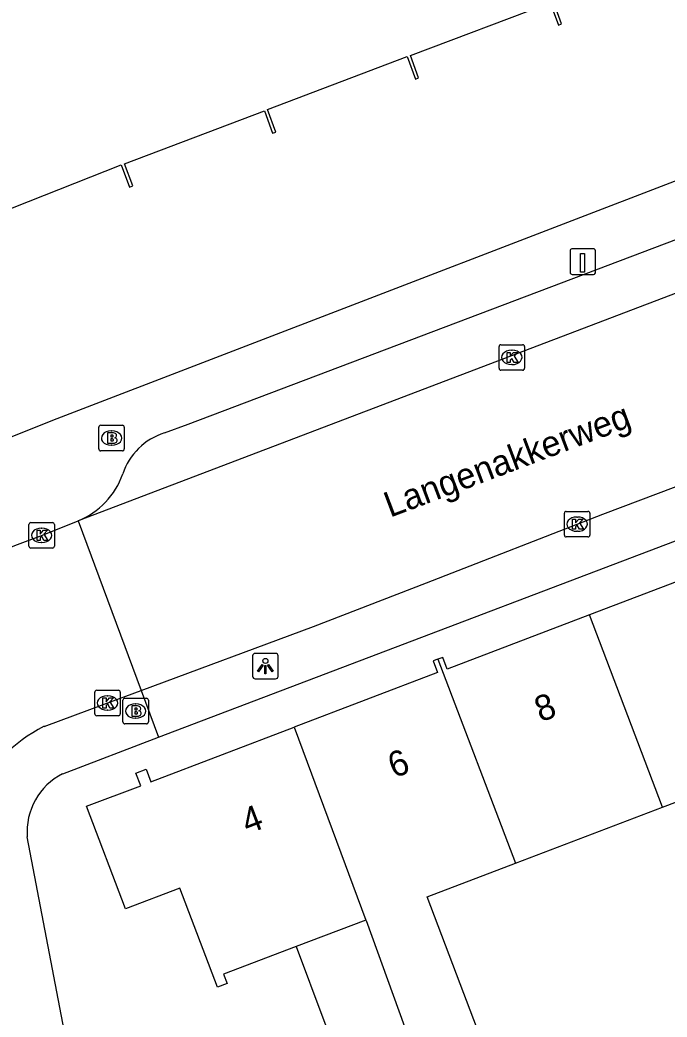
# Model space of a CAD drawing. Extents: x 159265 to 160143, y 383413 to 384319.
# Drawn here: x 159358.01 to 159383.4, y 383870.92 to 383910.01 of the extents above; entities that cross this region are included whole.
import ezdxf

# ---------------------------------------------------------------- set-up
doc = ezdxf.new("R2010")
doc.units = 0
for name, color, linetype in [('IMGEO_Brandkraan', 7, 'Continuous'), ('IMGEO_Kolk', 7, 'Continuous'), ('IMGEO_Laadpaal', 7, 'Continuous'), ('IMGEO_Lichtpunt', 7, 'Continuous'), ('IMGEO_Muur', 7, 'Continuous'), ('IMGEO_Openbare_ruimte_label', 7, 'Continuous'), ('IMGEO_Pand', 7, 'Continuous'), ('IMGEO_Pand_nummerreeks', 7, 'Continuous'), ('IMGEO_Rijbaan_lokaal_open', 7, 'Continuous'), ('IMGEO_Voetpad_open', 7, 'Continuous')]:
    doc.layers.add(name, color=color, linetype=linetype)

msp = doc.modelspace()

# ---------------------------------------------------------------- linework, layer by layer
at = {"layer": 'IMGEO_Brandkraan'}
for p, q in [((159361.103, 383893.192), (159361.103, 383894.044)), ((159361.178, 383894.118), (159362.03, 383894.118)), ((159362.104, 383894.044), (159362.104, 383893.192)), ((159361.591, 383893.898), (159361.616, 383893.898)), ((159361.614, 383893.338), (159361.589, 383893.338)), ((159362.03, 383893.118), (159361.178, 383893.118)), ((159362.122, 383883.413), (159362.974, 383883.413)), ((159362.047, 383882.487), (159362.047, 383883.339)), ((159362.535, 383883.193), (159362.56, 383883.193)), ((159363.048, 383883.339), (159363.048, 383882.487)), ((159362.558, 383882.633), (159362.533, 383882.633)), ((159362.974, 383882.413), (159362.122, 383882.413))]:
    msp.add_line(p, q, dxfattribs=at)
for points in [[(159361.103, 383893.192), (159361.103, 383894.044)], [(159361.178, 383894.118), (159362.03, 383894.118)], [(159362.104, 383894.044), (159362.104, 383893.192)], [(159361.451, 383893.818), (159361.451, 383893.418), (159361.664, 383893.418)], [(159361.682, 383893.818), (159361.451, 383893.818)], [(159361.63, 383893.737), (159361.576, 383893.737), (159361.576, 383893.661)], [(159361.576, 383893.661), (159361.629, 383893.661)], [(159361.638, 383893.585), (159361.576, 383893.585), (159361.576, 383893.504)], [(159361.576, 383893.504), (159361.638, 383893.504)], [(159362.03, 383893.118), (159361.178, 383893.118)], [(159362.122, 383883.413), (159362.974, 383883.413)], [(159362.047, 383882.487), (159362.047, 383883.339)], [(159362.395, 383883.113), (159362.395, 383882.713), (159362.608, 383882.713)], [(159362.626, 383883.113), (159362.395, 383883.113)], [(159362.574, 383883.032), (159362.52, 383883.032), (159362.52, 383882.956)], [(159363.048, 383883.339), (159363.048, 383882.487)], [(159362.52, 383882.956), (159362.573, 383882.956)], [(159362.582, 383882.88), (159362.52, 383882.88), (159362.52, 383882.799)], [(159362.52, 383882.799), (159362.582, 383882.799)], [(159362.974, 383882.413), (159362.122, 383882.413)]]:
    msp.add_lwpolyline(points, dxfattribs=at)
for centre, radius, start, end in [((159361.18, 383894.042), 0.0765, 91.552, 178.448), ((159361.18, 383894.042), 0.0765, 91.552, 178.448), ((159362.028, 383894.042), 0.0765, 1.552, 88.448), ((159362.028, 383894.042), 0.0765, 1.552, 88.448), ((159361.631, 383893.699), 0.0379, 267.8285, 90.9355), ((159361.639, 383893.544), 0.0404, 269.8759, 90.5077), ((159361.686, 383893.673), 0.145, 59.4692, 91.5367), ((159361.711, 383893.72), 0.0922, 285.5137, 58.1501), ((159361.716, 383893.528), 0.105, 301.3115, 78.989), ((159361.18, 383893.194), 0.0765, 181.552, 268.448), ((159361.18, 383893.194), 0.0765, 181.552, 268.448), ((159361.67, 383893.669), 0.251, 268.6676, 293.5347), ((159362.028, 383893.194), 0.0765, 271.552, 358.448), ((159362.028, 383893.194), 0.0765, 271.552, 358.448), ((159362.124, 383883.337), 0.0765, 91.552, 178.448), ((159362.124, 383883.337), 0.0765, 91.552, 178.448), ((159362.972, 383883.337), 0.0765, 1.552, 88.448), ((159362.972, 383883.337), 0.0765, 1.552, 88.448), ((159362.575, 383882.994), 0.0379, 267.8285, 90.9355), ((159362.63, 383882.968), 0.145, 59.4692, 91.5367), ((159362.655, 383883.015), 0.0922, 285.5137, 58.1501), ((159362.583, 383882.839), 0.0404, 269.8759, 90.5077), ((159362.614, 383882.964), 0.251, 268.6676, 293.5347), ((159362.66, 383882.823), 0.105, 301.3115, 78.989), ((159362.124, 383882.489), 0.0765, 181.552, 268.448), ((159362.124, 383882.489), 0.0765, 181.552, 268.448), ((159362.972, 383882.489), 0.0765, 271.552, 358.448), ((159362.972, 383882.489), 0.0765, 271.552, 358.448)]:
    msp.add_arc(centre, radius, start, end, dxfattribs=at)
for centre, major_axis, ratio, start_param, end_param in [((159361.59, 383893.618), (-0.387, 0.002), 0.722429, 4.712389, 7.853982), ((159361.615, 383893.618), (-0.39, 0.002), 0.717154, 1.570796, 4.712389), ((159362.534, 383882.913), (-0.387, 0.002), 0.722429, 4.712389, 7.853982), ((159362.559, 383882.913), (-0.39, 0.002), 0.717154, 1.570796, 4.712389)]:
    msp.add_ellipse(centre, major_axis=major_axis, ratio=ratio, start_param=start_param, end_param=end_param, dxfattribs=at)
at = {"layer": 'IMGEO_Kolk'}
for p, q in [((159376.804, 383896.354), (159376.804, 383897.206)), ((159376.879, 383897.28), (159377.731, 383897.28)), ((159377.292, 383897.06), (159377.317, 383897.06)), ((159377.805, 383897.206), (159377.805, 383896.354)), ((159377.731, 383896.28), (159376.879, 383896.28)), ((159377.315, 383896.5), (159377.29, 383896.5)), ((159379.367, 383889.817), (159379.367, 383890.669)), ((159379.442, 383890.743), (159380.294, 383890.743)), ((159379.855, 383890.523), (159379.88, 383890.523)), ((159380.368, 383890.669), (159380.368, 383889.817)), ((159358.359, 383889.379), (159358.359, 383890.231)), ((159358.434, 383890.305), (159359.286, 383890.305)), ((159358.847, 383890.085), (159358.872, 383890.085)), ((159359.36, 383890.231), (159359.36, 383889.379)), ((159380.294, 383889.743), (159379.442, 383889.743)), ((159379.878, 383889.963), (159379.853, 383889.963)), ((159359.286, 383889.305), (159358.434, 383889.305)), ((159358.87, 383889.525), (159358.845, 383889.525)), ((159360.945, 383882.805), (159360.945, 383883.657)), ((159361.02, 383883.731), (159361.872, 383883.731)), ((159361.433, 383883.511), (159361.458, 383883.511)), ((159361.946, 383883.657), (159361.946, 383882.805)), ((159361.872, 383882.731), (159361.02, 383882.731)), ((159361.456, 383882.951), (159361.431, 383882.951))]:
    msp.add_line(p, q, dxfattribs=at)
for points in [[(159376.804, 383896.354), (159376.804, 383897.206)], [(159376.879, 383897.28), (159377.731, 383897.28)], [(159377.805, 383897.206), (159377.805, 383896.354)], [(159377.125, 383896.98), (159377.248, 383896.98), (159377.248, 383896.829), (159377.378, 383896.98), (159377.542, 383896.98), (159377.396, 383896.829), (159377.549, 383896.58), (159377.397, 383896.58), (159377.312, 383896.744), (159377.248, 383896.677), (159377.248, 383896.58), (159377.125, 383896.58), (159377.125, 383896.98)], [(159377.731, 383896.28), (159376.879, 383896.28)], [(159379.367, 383889.817), (159379.367, 383890.669)], [(159379.442, 383890.743), (159380.294, 383890.743)], [(159379.688, 383890.443), (159379.811, 383890.443), (159379.811, 383890.292), (159379.941, 383890.443), (159380.105, 383890.443), (159379.959, 383890.292), (159380.112, 383890.043), (159379.96, 383890.043), (159379.875, 383890.207), (159379.811, 383890.14), (159379.811, 383890.043), (159379.688, 383890.043), (159379.688, 383890.443)], [(159380.368, 383890.669), (159380.368, 383889.817)], [(159358.359, 383889.379), (159358.359, 383890.231)], [(159358.434, 383890.305), (159359.286, 383890.305)], [(159359.36, 383890.231), (159359.36, 383889.379)], [(159358.68, 383890.005), (159358.803, 383890.005), (159358.803, 383889.854), (159358.933, 383890.005), (159359.097, 383890.005), (159358.951, 383889.854), (159359.104, 383889.605), (159358.952, 383889.605), (159358.867, 383889.769), (159358.803, 383889.702), (159358.803, 383889.605), (159358.68, 383889.605), (159358.68, 383890.005)], [(159380.294, 383889.743), (159379.442, 383889.743)], [(159359.286, 383889.305), (159358.434, 383889.305)], [(159360.945, 383882.805), (159360.945, 383883.657)], [(159361.02, 383883.731), (159361.872, 383883.731)], [(159361.266, 383883.431), (159361.389, 383883.431), (159361.389, 383883.28), (159361.519, 383883.431), (159361.683, 383883.431), (159361.537, 383883.28), (159361.69, 383883.031), (159361.538, 383883.031), (159361.453, 383883.195), (159361.389, 383883.128), (159361.389, 383883.031), (159361.266, 383883.031), (159361.266, 383883.431)], [(159361.946, 383883.657), (159361.946, 383882.805)], [(159361.872, 383882.731), (159361.02, 383882.731)]]:
    msp.add_lwpolyline(points, dxfattribs=at)
for centre, start, end in [((159376.881, 383897.204), 91.552, 178.448), ((159376.881, 383897.204), 91.552, 178.448), ((159377.729, 383897.204), 1.552, 88.448), ((159377.729, 383897.204), 1.552, 88.448), ((159376.881, 383896.356), 181.552, 268.448), ((159376.881, 383896.356), 181.552, 268.448), ((159377.729, 383896.356), 271.552, 358.448), ((159377.729, 383896.356), 271.552, 358.448), ((159379.444, 383890.667), 91.552, 178.448), ((159379.444, 383890.667), 91.552, 178.448), ((159380.292, 383890.667), 1.552, 88.448), ((159380.292, 383890.667), 1.552, 88.448), ((159358.436, 383890.229), 91.552, 178.448), ((159358.436, 383890.229), 91.552, 178.448), ((159359.284, 383890.229), 1.552, 88.448), ((159359.284, 383890.229), 1.552, 88.448), ((159379.444, 383889.819), 181.552, 268.448), ((159379.444, 383889.819), 181.552, 268.448), ((159380.292, 383889.819), 271.552, 358.448), ((159380.292, 383889.819), 271.552, 358.448), ((159358.436, 383889.381), 181.552, 268.448), ((159358.436, 383889.381), 181.552, 268.448), ((159359.284, 383889.381), 271.552, 358.448), ((159359.284, 383889.381), 271.552, 358.448), ((159361.022, 383883.655), 91.552, 178.448), ((159361.022, 383883.655), 91.552, 178.448), ((159361.87, 383883.655), 1.552, 88.448), ((159361.87, 383883.655), 1.552, 88.448), ((159361.022, 383882.807), 181.552, 268.448), ((159361.022, 383882.807), 181.552, 268.448), ((159361.87, 383882.807), 271.552, 358.448), ((159361.87, 383882.807), 271.552, 358.448)]:
    msp.add_arc(centre, 0.0765, start, end, dxfattribs=at)
for centre, major_axis, ratio, start_param, end_param in [((159377.291, 383896.78), (-0.387, 0.002), 0.722429, 4.712389, 7.853982), ((159377.316, 383896.78), (-0.39, 0.002), 0.717154, 1.570796, 4.712389), ((159379.854, 383890.243), (-0.387, 0.002), 0.722429, 4.712389, 7.853982), ((159379.879, 383890.243), (-0.39, 0.002), 0.717154, 1.570796, 4.712389), ((159358.846, 383889.805), (-0.387, 0.002), 0.722429, 4.712389, 7.853982), ((159358.871, 383889.805), (-0.39, 0.002), 0.717154, 1.570796, 4.712389), ((159361.432, 383883.231), (-0.387, 0.002), 0.722429, 4.712389, 7.853982), ((159361.457, 383883.231), (-0.39, 0.002), 0.717154, 1.570796, 4.712389)]:
    msp.add_ellipse(centre, major_axis=major_axis, ratio=ratio, start_param=start_param, end_param=end_param, dxfattribs=at)
at = {"layer": 'IMGEO_Laadpaal'}
for p, q in [((159380.505, 383901.038), (159379.664, 383901.038)), ((159380.505, 383901.038), (159379.664, 383901.038)), ((159380.589, 383900.122), (159380.589, 383900.963)), ((159380.589, 383900.122), (159380.589, 383900.963)), ((159379.589, 383900.954), (159379.589, 383900.113)), ((159379.589, 383900.954), (159379.589, 383900.113)), ((159379.673, 383900.038), (159380.514, 383900.038)), ((159379.673, 383900.038), (159380.514, 383900.038))]:
    msp.add_line(p, q, dxfattribs=at)
msp.add_lwpolyline([(159380.004, 383900.851), (159380.164, 383900.851), (159380.164, 383900.118), (159380.004, 383900.118), (159380.004, 383900.851)], dxfattribs=at)
for centre, start, end in [((159379.667, 383900.96), 92.4484, 184.2845), ((159379.667, 383900.96), 92.4484, 184.2845), ((159380.511, 383900.96), 2.4484, 94.2845), ((159380.511, 383900.96), 2.4484, 94.2845), ((159379.667, 383900.116), 182.4484, 274.2845), ((159379.667, 383900.116), 182.4484, 274.2845), ((159380.511, 383900.116), 272.4484, 4.2845), ((159380.511, 383900.116), 272.4484, 4.2845)]:
    msp.add_arc(centre, 0.0779, start, end, dxfattribs=at)
at = {"layer": 'IMGEO_Lichtpunt'}
for p, q in [((159367.139, 383885.081), (159367.139, 383884.274)), ((159367.139, 383885.081), (159367.139, 383884.274)), ((159368.041, 383885.176), (159367.233, 383885.176)), ((159368.041, 383885.176), (159367.233, 383885.176)), ((159368.135, 383884.274), (159368.135, 383885.081)), ((159368.135, 383884.274), (159368.135, 383885.081)), ((159367.233, 383884.18), (159368.041, 383884.18)), ((159367.233, 383884.18), (159368.041, 383884.18))]:
    msp.add_line(p, q, dxfattribs=at)
for points in [[(159367.513, 383884.745), (159367.552, 383884.717), (159367.364, 383884.455), (159367.326, 383884.482), (159367.513, 383884.745)], [(159367.615, 383884.697), (159367.662, 383884.697), (159367.662, 383884.375), (159367.615, 383884.375), (159367.615, 383884.697)], [(159367.725, 383884.717), (159367.763, 383884.744), (159367.95, 383884.482), (159367.911, 383884.454), (159367.725, 383884.717)]]:
    msp.add_lwpolyline(points, dxfattribs=at)
msp.add_circle((159367.638, 383884.879), 0.0994, dxfattribs=at)
for centre, start, end in [((159367.233, 383885.081), 90, 180), ((159367.233, 383885.081), 90, 180), ((159368.041, 383885.081), 0, 90), ((159368.041, 383885.081), 0, 90), ((159367.233, 383884.274), 180, 270), ((159367.233, 383884.274), 180, 270), ((159368.041, 383884.274), 270, 0), ((159368.041, 383884.274), 270, 360)]:
    msp.add_arc(centre, 0.0946, start, end, dxfattribs=at)
at = {"layer": 'IMGEO_Muur'}
msp.add_lwpolyline([(159361.194, 383862.82), (159359.054, 383874.019)], dxfattribs=at)
at = {"layer": 'IMGEO_Pand'}
for points in [[(159356.921, 383901.091), (159356.515, 383902.181), (159361.985, 383904.332), (159362.313, 383903.46), (159362.437, 383903.507), (159362.107, 383904.377), (159367.6, 383906.453), (159367.917, 383905.574), (159368.044, 383905.618), (159367.722, 383906.498), (159373.204, 383908.575), (159373.531, 383907.692), (159373.651, 383907.742), (159373.326, 383908.62), (159378.815, 383910.684), (159379.136, 383909.813), (159379.258, 383909.858), (159378.937, 383910.729)], [(159385.945, 383889.359), (159385.746, 383889.283), (159385.928, 383888.803), (159380.35, 383886.681)], [(159380.35, 383886.681), (159374.772, 383884.558), (159374.596, 383885.02), (159374.408, 383884.949)], [(159383.217, 383879.139), (159380.35, 383886.681)], [(159374.408, 383884.949), (159374.219, 383884.877), (159374.393, 383884.42), (159368.772, 383882.281)], [(159374.408, 383884.949), (159377.449, 383876.947)], [(159368.849, 383873.679), (159365.998, 383872.596), (159366.138, 383872.23), (159365.755, 383872.084), (159364.276, 383875.969), (159362.156, 383875.163), (159360.626, 383879.181), (159362.747, 383879.988), (159362.561, 383880.477), (159362.965, 383880.63), (159363.151, 383880.142), (159368.772, 383882.281)], [(159368.772, 383882.281), (159371.584, 383874.719)], [(159383.217, 383879.139), (159388.995, 383881.334)], [(159377.449, 383876.947), (159383.217, 383879.139)], [(159380.322, 383869.052), (159376.97, 383867.779), (159373.982, 383875.629), (159377.449, 383876.947)], [(159371.584, 383874.719), (159368.849, 383873.679)], [(159371.584, 383874.719), (159371.589, 383874.706), (159374.381, 383867.004), (159374.446, 383866.82), (159375.271, 383864.492)], [(159368.849, 383873.679), (159369.937, 383870.778), (159371.476, 383866.674), (159361.194, 383862.82)]]:
    msp.add_lwpolyline(points, dxfattribs=at)
at = {"layer": 'IMGEO_Rijbaan_lokaal_open'}
for points in [[(159408.89, 383908.872), (159360.29, 383890.372)], [(159362.763, 383883.722), (159369.522, 383886.236), (159373.965, 383887.945), (159380.876, 383890.636), (159392.067, 383894.857), (159402.096, 383898.646), (159407.335, 383900.738), (159408.31, 383901.097)], [(159353.851, 383887.296), (159355.133, 383888.057), (159356.469, 383888.77), (159357.368, 383889.209), (159357.811, 383889.405), (159358.892, 383889.815), (159360.29, 383890.372)], [(159360.29, 383890.372), (159362.763, 383883.722)], [(159358.957, 383882.315), (159361.319, 383883.185), (159362.763, 383883.722)]]:
    msp.add_lwpolyline(points, dxfattribs=at)
msp.add_arc((159361.741, 383876.818), 6.162, 116.8603, 190.6332, dxfattribs=at)
at = {"layer": 'IMGEO_Voetpad_open'}
for points in [[(159412.277, 383914.472), (159403.464, 383911.157), (159391.087, 383906.525), (159359.454, 383894.369), (159357.328, 383893.521), (159354.634, 383892.446)], [(159363.675, 383893.818), (159364.612, 383894.169), (159398.907, 383907.143), (159405.054, 383909.537)], [(159363.447, 383881.885), (159417.717, 383902.495)], [(159362.763, 383883.722), (159363.447, 383881.885)], [(159359.686, 383880.457), (159363.447, 383881.885)], [(159361.194, 383862.82), (159359.054, 383874.019), (159358.297, 383877.978)]]:
    msp.add_lwpolyline(points, dxfattribs=at)
for centre, radius, start, end in [((159364.424, 383891.427), 2.506, 107.4042, 161.746), ((159359.133, 383893.233), 3.086, 292.023, 340.6859), ((159360.856, 383878.173), 2.567, 117.1268, 184.3488)]:
    msp.add_arc(centre, radius, start, end, dxfattribs=at)

# ---------------------------------------------------------------- texts
at = {"layer": 'IMGEO_Openbare_ruimte_label'}
msp.add_text('Langenakkerweg', height=1, rotation=20.6835, dxfattribs=at).set_placement((159372.529, 383890.493))
at = {"layer": 'IMGEO_Pand_nummerreeks'}
for s, rotation, p in [('8', 20.8903, (159378.437, 383882.466)), ('6', 20.89, (159372.685, 383880.27)), ('4', 20.89, (159366.937, 383878.077))]:
    msp.add_text(s, height=1, rotation=rotation, dxfattribs=at).set_placement(p)

doc.saveas('drawing.dxf')
